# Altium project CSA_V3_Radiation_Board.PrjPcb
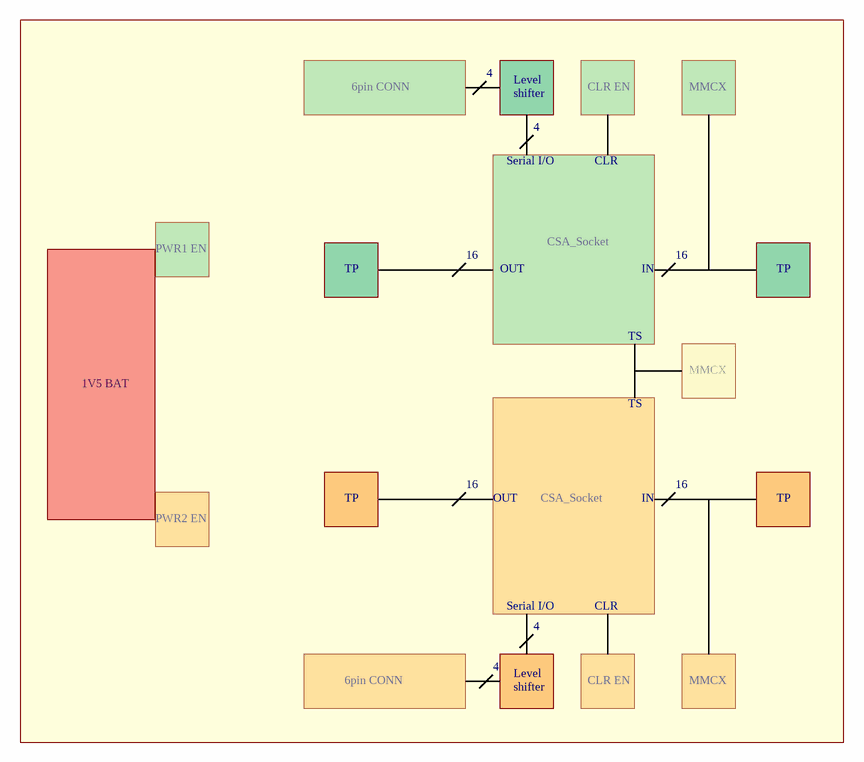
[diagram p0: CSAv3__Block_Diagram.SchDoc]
Approved_By: Gary S. Varner; BoardName: CSA_V3_Radiation_Board; Designer: AS/KPL; Drawn_By: KPL; IDLnum: IDL_16_016; ProjectName1: CSA_V3; RevNum: A
4 sheets, 186 parts. Net scope: flat (ports and power ports of the same name join across sheets).
Board file: IDL_16_016.PcbDoc
Sheets:
  PRJHdr_IDL_16_016.SchDoc
  CSAv3__Block_Diagram.SchDoc
  CSAv3_A1_Socket1.SchDoc
  CSAv3_A2_Socket2.SchDoc

## Sheet PRJHdr_IDL_16_016.SchDoc: Title_doc_parameter!
size 401 x 291 mm; DocumentNumber: 1; SheetNumber: 1; SheetTotal: 4; Project_IT-Code: XXXX

## Sheet CSAv3__Block_Diagram.SchDoc: Functional Block Schematic
size 401 x 291 mm; DocumentNumber: 2; SheetNumber: 2; SheetTotal: 4; PageSetup: Record=PageOptions¦CenterHorizontal=True¦CenterVertical=True¦PrintScale=1.00¦XCorrection=1.00¦YCorrection=1.00¦PrintKind=1¦BorderSize=5000000¦LeftOffset=0¦BottomOffset=0¦Orientation=2¦PaperLength=1000¦PaperWidth=1000¦Scale=100¦PaperSource=7¦PrintQuality=-3¦MediaType=1¦DitherType=10¦PrintScaleMode=1¦PaperKind=A4¦PaperIndex=9

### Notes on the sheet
- 6pin CONN
- 4
- Level
- shifter
- CLR EN
- MMCX
- Serial I/O
- CLR
- PWR1 EN
- CSA_Socket
- TP
- 16
- OUT
- IN
- 1V5 BAT
- TS
- PWR2 EN

## Sheet CSAv3_A1_Socket1.SchDoc: CSA_V3 Socket1/TS
size 401 x 291 mm; DocumentNumber: 3; SheetNumber: 3; SheetTotal: 4
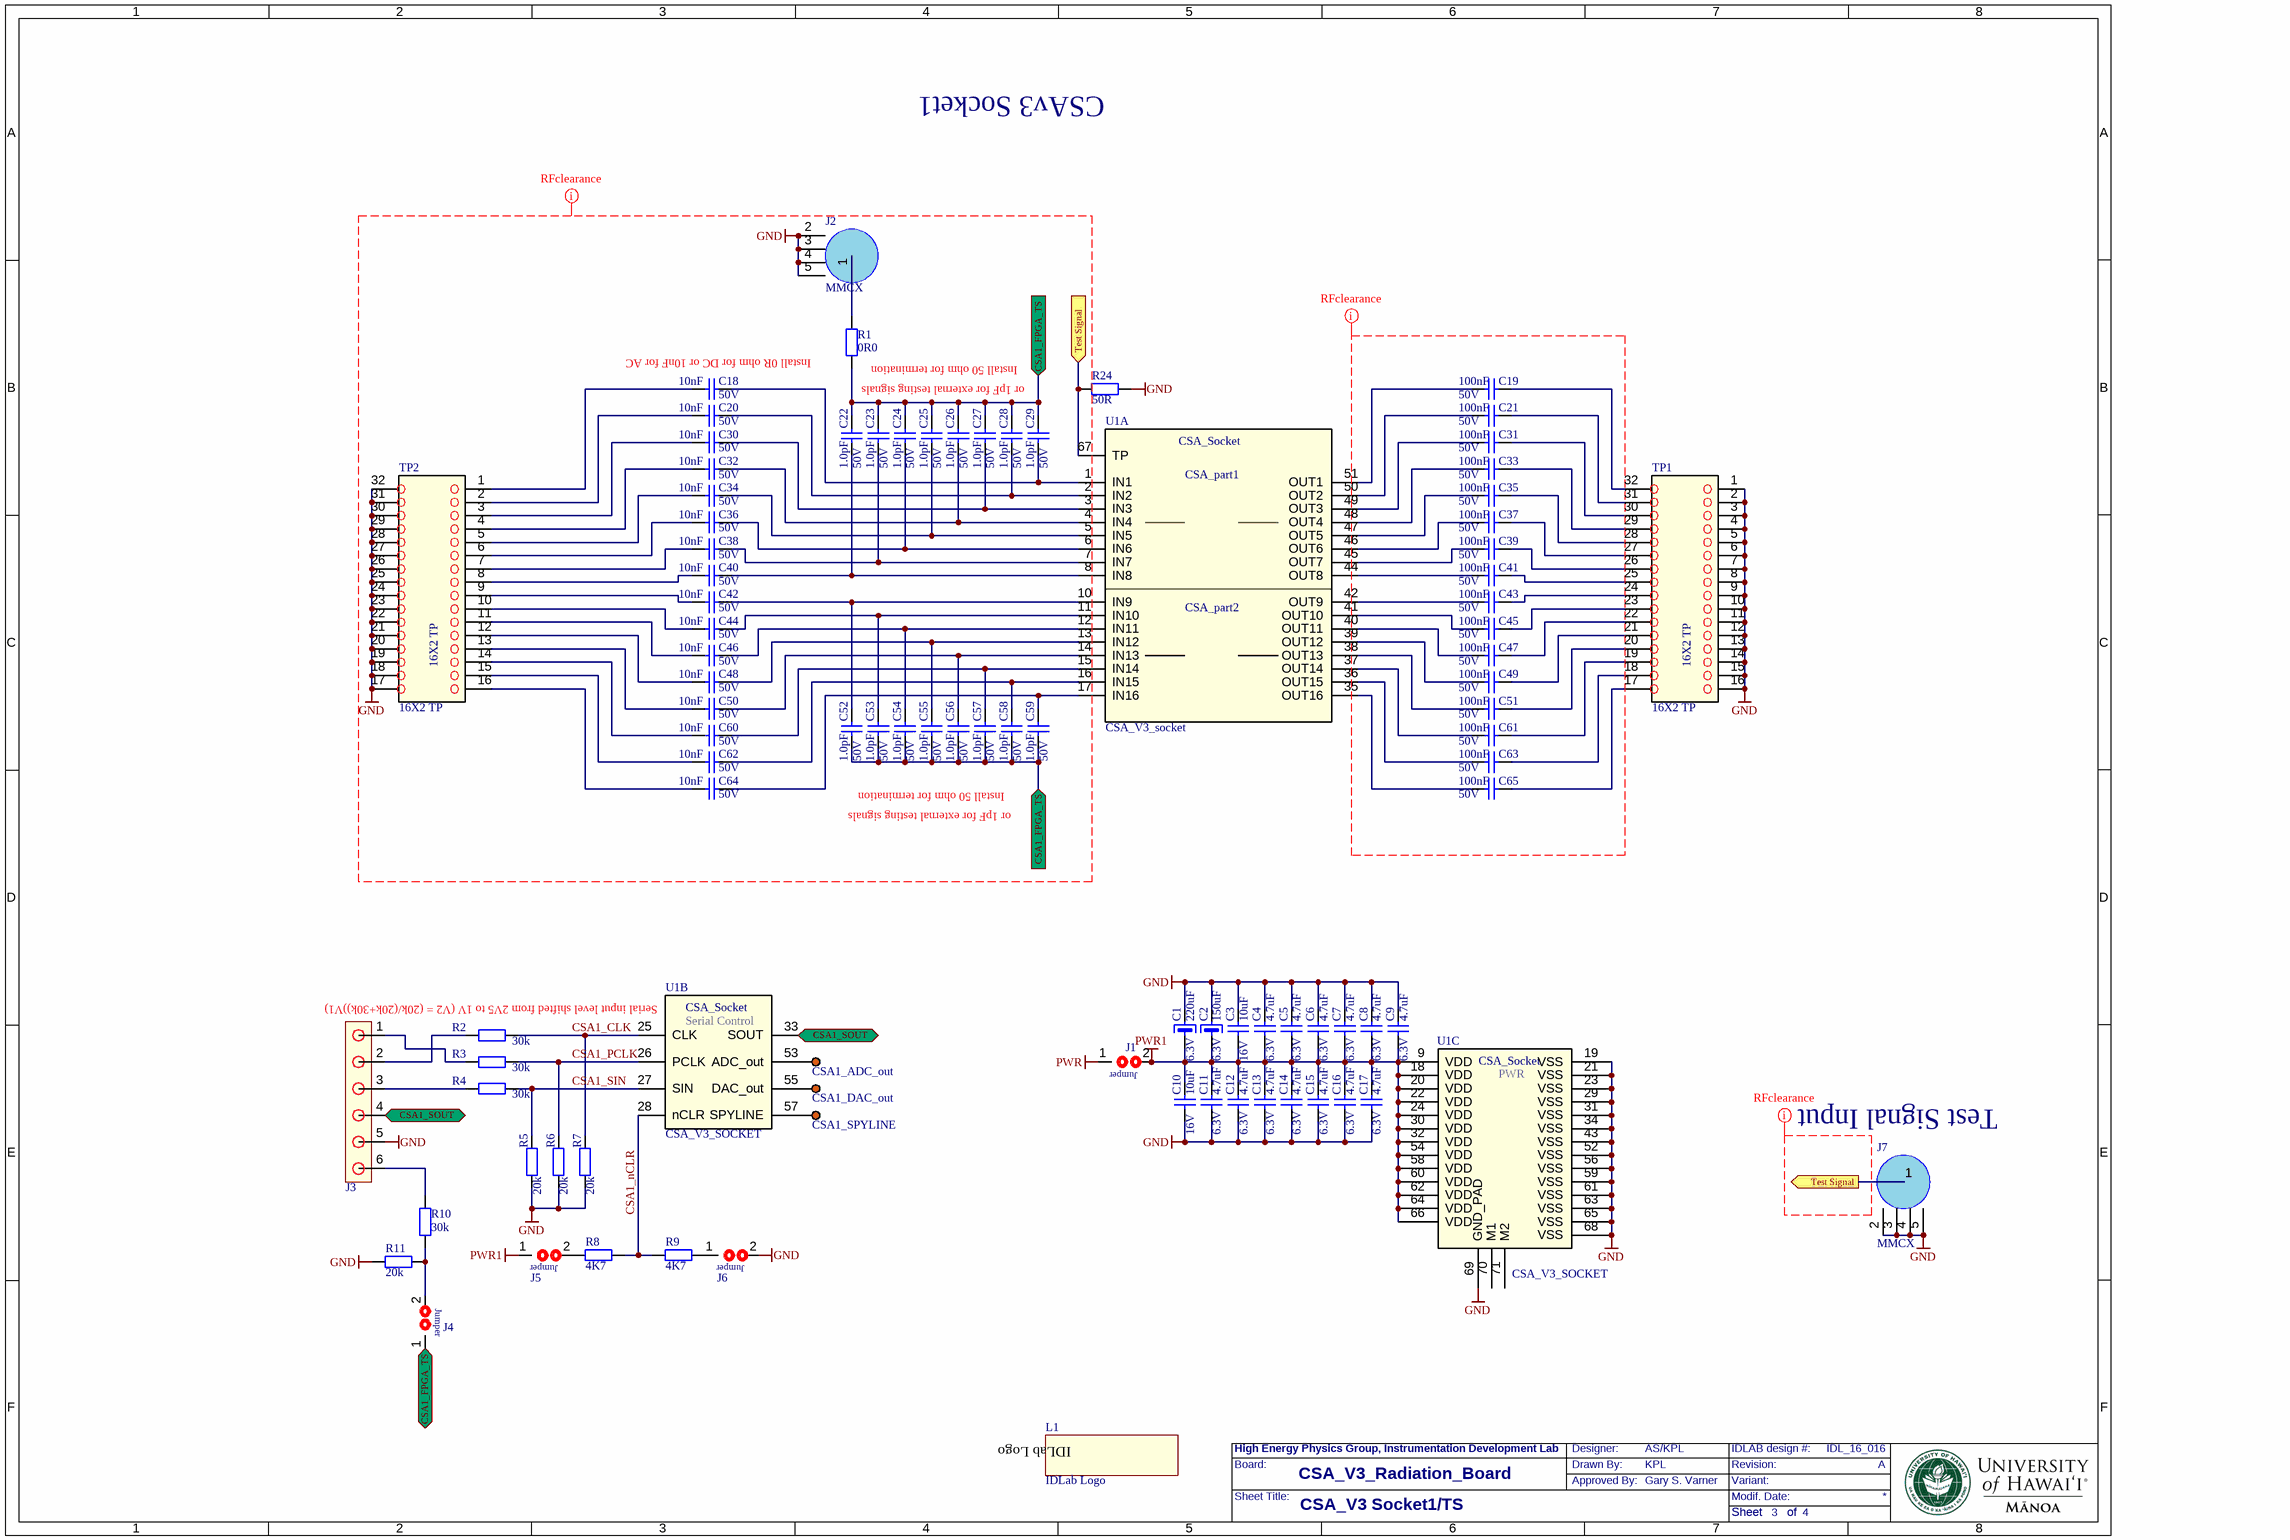
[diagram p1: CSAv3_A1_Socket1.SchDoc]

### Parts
C1  220uF  Voltage rating: 6.3V  [CTC-D7343-43]
C2  150uF  Voltage: 6.3V  [CTC-B3528-21]
C3  10uF  Voltage rating: 16V  [CC1206N1R]
C4  4.7uF  Voltage rating: 6.3V  [CC0402N1R]
C5  4.7uF  Voltage rating: 6.3V  [CC0402N1R]
C6  4.7uF  Voltage rating: 6.3V  [CC0402N1R]
C7  4.7uF  Voltage rating: 6.3V  [CC0402N1R]
C8  4.7uF  Voltage rating: 6.3V  [CC0402N1R]
C9  4.7uF  Voltage rating: 6.3V  [CC0402N1R]
C10  10uF  Voltage rating: 16V  [CC1206N1R]
C11  4.7uF  Voltage rating: 6.3V  [CC0402N1R]
C12  4.7uF  Voltage rating: 6.3V  [CC0402N1R]
C13  4.7uF  Voltage rating: 6.3V  [CC0402N1R]
C14  4.7uF  Voltage rating: 6.3V  [CC0402N1R]
C15  4.7uF  Voltage rating: 6.3V  [CC0402N1R]
C16  4.7uF  Voltage rating: 6.3V  [CC0402N1R]
C17  4.7uF  Voltage rating: 6.3V  [CC0402N1R]
C18  10nF  Voltage rating: 50V  [CC0402N1X]
C19  100nF  Voltage rating: 50V  [CC0402RF1]
C20  10nF  Voltage rating: 50V  [CC0402N1X]
C21  100nF  Voltage rating: 50V  [CC0402RF1]
C22  1.0pF  Voltage rating: 50V  [CC0402RF1]
C23  1.0pF  Voltage rating: 50V  [CC0402RF1]
C24  1.0pF  Voltage rating: 50V  [CC0402RF1]
C25  1.0pF  Voltage rating: 50V  [CC0402RF1]
C26  1.0pF  Voltage rating: 50V  [CC0402RF1]
C27  1.0pF  Voltage rating: 50V  [CC0402RF1]
C28  1.0pF  Voltage rating: 50V  [CC0402RF1]
C29  1.0pF  Voltage rating: 50V  [CC0402RF1]
C30  10nF  Voltage rating: 50V  [CC0402N1X]
C31  100nF  Voltage rating: 50V  [CC0402RF1]
C32  10nF  Voltage rating: 50V  [CC0402N1X]
C33  100nF  Voltage rating: 50V  [CC0402RF1]
C34  10nF  Voltage rating: 50V  [CC0402N1X]
C35  100nF  Voltage rating: 50V  [CC0402RF1]
C36  10nF  Voltage rating: 50V  [CC0402N1X]
C37  100nF  Voltage rating: 50V  [CC0402RF1]
C38  10nF  Voltage rating: 50V  [CC0402N1X]
C39  100nF  Voltage rating: 50V  [CC0402RF1]
C40  10nF  Voltage rating: 50V  [CC0402N1X]
C41  100nF  Voltage rating: 50V  [CC0402RF1]
C42  10nF  Voltage rating: 50V  [CC0402N1X]
C43  100nF  Voltage rating: 50V  [CC0402RF1]
C44  10nF  Voltage rating: 50V  [CC0402N1X]
C45  100nF  Voltage rating: 50V  [CC0402RF1]
C46  10nF  Voltage rating: 50V  [CC0402N1X]
C47  100nF  Voltage rating: 50V  [CC0402RF1]
C48  10nF  Voltage rating: 50V  [CC0402N1X]
C49  100nF  Voltage rating: 50V  [CC0402RF1]
C50  10nF  Voltage rating: 50V  [CC0402N1X]
C51  100nF  Voltage rating: 50V  [CC0402RF1]
C52  1.0pF  Voltage rating: 50V  [CC0402RF1]
C53  1.0pF  Voltage rating: 50V  [CC0402RF1]
C54  1.0pF  Voltage rating: 50V  [CC0402RF1]
C55  1.0pF  Voltage rating: 50V  [CC0402RF1]
C56  1.0pF  Voltage rating: 50V  [CC0402RF1]
C57  1.0pF  Voltage rating: 50V  [CC0402RF1]
C58  1.0pF  Voltage rating: 50V  [CC0402RF1]
C59  1.0pF  Voltage rating: 50V  [CC0402RF1]
C60  10nF  Voltage rating: 50V  [CC0402N1X]
C61  100nF  Voltage rating: 50V  [CC0402RF1]
C62  10nF  Voltage rating: 50V  [CC0402N1X]
C63  100nF  Voltage rating: 50V  [CC0402RF1]
C64  10nF  Voltage rating: 50V  [CC0402N1X]
C65  100nF  Voltage rating: 50V  [CC0402RF1]
CSA1_ADC_out  SP1.5S  [SP1.5SQ]  (value not drawn)  (no BOM)
CSA1_DAC_out  SP1.5S  [SP1.5SQ]  (value not drawn)  (no BOM)
CSA1_SPYLINE  SP1.5S  [SP1.5SQ]  (value not drawn)  (no BOM)
J1  2pin_Jumper  [2pin_jumper]  (value not drawn)
J2  MMCX  [MMCX_VERTICAL_THROUGH_HOLE]
J3  Male  (value not drawn)
J4  2pin_Jumper  [2pin_jumper]  (value not drawn)
J5  2pin_Jumper  [2pin_jumper]  (value not drawn)
J6  2pin_Jumper  [2pin_jumper]  (value not drawn)
J7  MMCX  [MMCX_VERTICAL_THROUGH_HOLE]
L1  IDLab Logo  [IDLab logo]
R1  0R0  [RC0603N1R]
R2  30k  [RC0603RF1]
R3  30k  [RC0603RF1]
R4  30k  [RC0603RF1]
R5  20k  [RC0603RF1]
R6  20k  [RC0603RF1]
R7  20k  [RC0603RF1]
R8  4K7  [RC0402N1R]
R9  4K7  [RC0402N1R]
R10  30k  [RC0603RF1]
R11  20k  [RC0603RF1]
R24  50R  [RC0402RF1]
TP1  16X2 TP  [16X2 TP]
TP2  16X2 TP  [16X2 TP]
U1  CSA_V3_socket  [SOCKET_QFN-68BT-0.5-01]  (parts A,B,C of 3)

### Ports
CSA1_FPGA_TS (in), CSA1_FPGA_TS (out), CSA1_SOUT (in), CSA1_SOUT (out), Test Signal (in), Test Signal (out)

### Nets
GND: C1.2 C2.2 C3.2 C4.2 C5.2 C6.2 C7.2 C8.2 C9.2 C10.1 C11.1 C12.1 C13.1 C14.1 C15.1 C16.1 C17.1 J2.2 J2.3 J2.4 J2.5 J3.5 J6.2 J7.2 J7.3 J7.4 J7.5 R5.1 R6.1 R7.1 R11.2 R24.1 TP1.1 TP1.2 TP1.3 TP1.4 TP1.5 TP1.6 TP1.7 TP1.8 TP1.9 TP1.10 TP1.11 TP1.12 TP1.13 TP1.14 TP1.15 TP1.16 TP2.17 TP2.18 TP2.19 TP2.20 TP2.21 TP2.22 TP2.23 TP2.24 TP2.25 TP2.26 TP2.27 TP2.28 TP2.29 TP2.30 TP2.31 TP2.32 U1.19(VSS) U1.21(VSS) U1.23(VSS) U1.29(VSS) U1.31(VSS) U1.34(VSS) U1.43(VSS) U1.52(VSS) U1.56(VSS) U1.59(VSS) U1.61(VSS) U1.63(VSS) U1.65(VSS) U1.68(VSS) U1.69(GND_PAD)
PWR: J1.1
PWR1: C1.1 C2.1 C3.1 C4.1 C5.1 C6.1 C7.1 C8.1 C9.1 C10.2 C11.2 C12.2 C13.2 C14.2 C15.2 C16.2 C17.2 J1.2 J5.1 U1.9(VDD) U1.18(VDD) U1.20(VDD) U1.22(VDD) U1.24(VDD) U1.30(VDD) U1.32(VDD) U1.54(VDD) U1.58(VDD) U1.60(VDD) U1.62(VDD) U1.64(VDD) U1.66(VDD)
CSA1_CLK: R2.2 R7.2 U1.25(CLK)  [project net CSA1_CLK_3]
CSA1_FPGA_TS: C22.2 C23.2 C24.2 C25.2 C26.2 C27.2 C28.2 C29.2 C52.1 C53.1 C54.1 C55.1 C56.1 C57.1 C58.1 C59.1 J4.1 R1.2 ; port CSA1_FPGA_TS
CSA1_nCLR: R8.1 R9.2 U1.28(nCLR)  [project net CSA1_nCLR_3]
CSA1_PCLK: R3.2 R6.2 U1.26(PCLK)  [project net CSA1_PCLK_3]
CSA1_SIN: R4.2 R5.2 U1.27(SIN)  [project net CSA1_SIN_3]
CSA1_SOUT: J3.4 U1.33(SOUT) ; port CSA1_SOUT
Test Signal: J7.1 R24.2 U1.67(TP) ; port Test Signal
NetC18_1: C18.1 TP2.1
NetC18_2: C18.2 C29.1 U1.1(IN1)
NetC19_1: C19.1 U1.51(OUT1)
NetC19_2: C19.2 TP1.32
NetC20_1: C20.1 TP2.2
NetC20_2: C20.2 C28.1 U1.2(IN2)
NetC21_1: C21.1 U1.50(OUT2)
NetC21_2: C21.2 TP1.31
NetC22_1: C22.1 C40.2 U1.8(IN8)
NetC23_1: C23.1 C38.2 U1.7(IN7)
NetC24_1: C24.1 C36.2 U1.6(IN6)
NetC25_1: C25.1 C34.2 U1.5(IN5)
NetC26_1: C26.1 C32.2 U1.4(IN4)
NetC27_1: C27.1 C30.2 U1.3(IN3)
NetC30_1: C30.1 TP2.3
NetC31_1: C31.1 U1.49(OUT3)
NetC31_2: C31.2 TP1.30
NetC32_1: C32.1 TP2.4
NetC33_1: C33.1 U1.48(OUT4)
NetC33_2: C33.2 TP1.29
NetC34_1: C34.1 TP2.5
NetC35_1: C35.1 U1.47(OUT5)
NetC35_2: C35.2 TP1.28
NetC36_1: C36.1 TP2.6
NetC37_1: C37.1 U1.46(OUT6)
NetC37_2: C37.2 TP1.27
NetC38_1: C38.1 TP2.7
NetC39_1: C39.1 U1.45(OUT7)
NetC39_2: C39.2 TP1.26
NetC40_1: C40.1 TP2.8
NetC41_1: C41.1 U1.44(OUT8)
NetC41_2: C41.2 TP1.25
NetC42_1: C42.1 TP2.9
NetC42_2: C42.2 C52.2 U1.10(IN9)
NetC43_1: C43.1 U1.42(OUT9)
NetC43_2: C43.2 TP1.24
NetC44_1: C44.1 TP2.10
NetC44_2: C44.2 C53.2 U1.11(IN10)
NetC45_1: C45.1 U1.41(OUT10)
NetC45_2: C45.2 TP1.23
NetC46_1: C46.1 TP2.11
NetC46_2: C46.2 C54.2 U1.12(IN11)
NetC47_1: C47.1 U1.40(OUT11)
NetC47_2: C47.2 TP1.22
NetC48_1: C48.1 TP2.12
NetC48_2: C48.2 C55.2 U1.13(IN12)
NetC49_1: C49.1 U1.39(OUT12)
NetC49_2: C49.2 TP1.21
NetC50_1: C50.1 TP2.13
NetC50_2: C50.2 C56.2 U1.14(IN13)
NetC51_1: C51.1 U1.38(OUT13)
NetC51_2: C51.2 TP1.20
NetC57_2: C57.2 C60.2 U1.15(IN14)
NetC58_2: C58.2 C62.2 U1.16(IN15)
NetC59_2: C59.2 C64.2 U1.17(IN16)
NetC60_1: C60.1 TP2.14
NetC61_1: C61.1 U1.37(OUT14)
NetC61_2: C61.2 TP1.19
NetC62_1: C62.1 TP2.15
NetC63_1: C63.1 U1.36(OUT15)
NetC63_2: C63.2 TP1.18
NetC64_1: C64.1 TP2.16
NetC65_1: C65.1 U1.35(OUT16)
NetC65_2: C65.2 TP1.17
NetCSA1_ADC_out_1: CSA1_ADC_out.1 U1.53(ADC_out)
NetCSA1_DAC_out_1: CSA1_DAC_out.1 U1.55(DAC_out)
NetCSA1_SPYLINE_1: CSA1_SPYLINE.1 U1.57(SPYLINE)
NetJ2_1: J2.1 R1.1
NetJ3_1: J3.1 R3.1
NetJ3_2: J3.2 R2.1
NetJ3_3: J3.3 R4.1
NetJ3_6: J3.6 R10.2
NetJ4_2: J4.2 R10.1 R11.1
NetJ5_2: J5.2 R8.2
NetJ6_1: J6.1 R9.1

Not connected (* = marked no-connect by the designer): U1 70(M1) 71(M2)

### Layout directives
net class RF: (no net found under the mark), GND

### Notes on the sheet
- CSAv3 Socket1
- (near C18) Install 0R ohm for DC or 10nF for AC
- (near R1) Install 50 ohm for termination
- or 1pF for external testing signals
- Install 50 ohm for termination
- Serial input level shifted from 2V5 to 1V (V2 = (20k/(20k+30k))V1)
- (near J7) Test Signal Input

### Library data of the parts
C1 = CAPT7343_220U_6.3V: 220µF 6.3V Aluminum - Polymer Capacitors; Manufacturer: Panasonic; Manufacturer No: EEF-UE0J221LR; Tech: SMDR
C2 = CAPT3528_150U6V3R0.5: 150µF Molded Tantalum Capacitors 6.3V 1411; Manufacturer: AVX; Manufacturer No: F930J157MBA; Comment2: 6.3V 0.5R  20%; Tech: SMDR
C3 C10 = CAPCC1206_10U_16VX7R: 10µF 16V Ceramic Capacitor X7R 1206; Manufacturer: TDK; Manufacturer No: C3216X7R1C106M160AC; Tech: SMDR
C4-C9 C11-C17 = CAPCC0402_4.7uF_6.3V: 4.7µF ±10% 6.3V X7R Ceramic Capacitor; Manufacturer: Samsung Electro-Mechanics America, Inc.; Manufacturer No: CL05A475KQ5NRNC; Tech: SMDR
C18 C20 C30 C32 C34 C36 C38 C40 C42 C44 C46 C48 C50 C60 C62 C64 = CAPCC0402_1_10.0N_50VX7R: Capacitor chip ceramic 0402 50V X7R; Manufacturer: Murata; Manufacturer No: GRM155R71H103KA88J; Tech: SMDR
C19 C21 C31 C33 C35 C37 C39 C41 C43 C45 C47 C49 C51 C61 C63 C65 = CAP0402_100N_50VX7R: Capacitor chip ceramic 0402 50V X7R; Manufacturer: TDK; Manufacturer No: C1005X7R1H104K050BB; Tech: SMDR
C22-C29 C52-C59 = CAP0402_1P_50VNP0: Capacitor chip ceramic 0402 50V NPO; Manufacturer: Murata; Manufacturer No: GRM1555C1H1R0CA01D; Tech: SMDR
CSA1_ADC_out CSA1_DAC_out CSA1_SPYLINE = SP1.5S: Wire solder pin 1.5mm; Sort: 610; Tech: THDW
J1 J4-J6 = 2pin_Jumper: 2 Positions Header, Unshrouded, Breakaway Connector 0.100" (2.54mm) Through Hole Tin; Manufacturer: Harwin Inc.; Manufacturer No: M20-9990246; Voltage rating: 50V
J2 J7 = MMCX: CONN MMCX JACK STR 50 OHM PCB; Manufacturer: Molex, LLC; Manufacturer part #: 0734151471
J3 = CONN_6pin_Molex 2.54mm: 6 Positions Header, Unshrouded Connector 0.100" (2.54mm) Through Hole Tin; Manufacturer: Molex, LLC; Manufacturer No: 0022232061
R1 = RES0603-0R0-1%100PPM: RES SMD 0.0OHM JUMPER 1/10W 0603; Manufacturer: Panasonic; Manufacturer No: ERJ-3GEY0R00V; Tech: SMDR
R2-R4 R10 = RES0603-30K-1%100PPM: RES SMD 30K OHM 1% 1/10W 0603; Manufacturer: Yageo; Manufacturer No: RC0603FR-0730KL; Tech: SMDR
R5-R7 R11 = RES0603-20K-1%100PPM: RES SMD 20K OHM 1% 1/10W 0603; Manufacturer: Yageo; Manufacturer No: RC0603FR-0720KL; Tech: SMDR
R8 R9 = RES0402-4.7K-1%100PPM: RES SMD 4.7K OHM 1% 1/10W 0402; Manufacturer: Panasonic; Manufacturer No: ERJ-2RKF4701X; Tech: SMDR
R24 = RES0402-50R-1%100PPM: RES SMD 49.9 OHM 1% 1/16W 0402; Manufacturer: Samsung Inc.; Manufacturer No: RC1005F49R9CS; Tech: SMDR
TP1 TP2 = TP 16X2: 16X2 TESTPOINTs; Voltage rating: 50V
U1 = CSA_V3_socket: Enplas IC Test & Burn-in Socket, for QFN68, MLP68, MLF68 package; Manufacturer: Enplas Co; Manufacturer No: QFN-68BT-0.5-01; Tech: through hole

## Sheet CSAv3_A2_Socket2.SchDoc: CSA_V3 Socket2/BATT_PWR
size 401 x 291 mm; DocumentNumber: 4; SheetNumber: 4; SheetTotal: 4
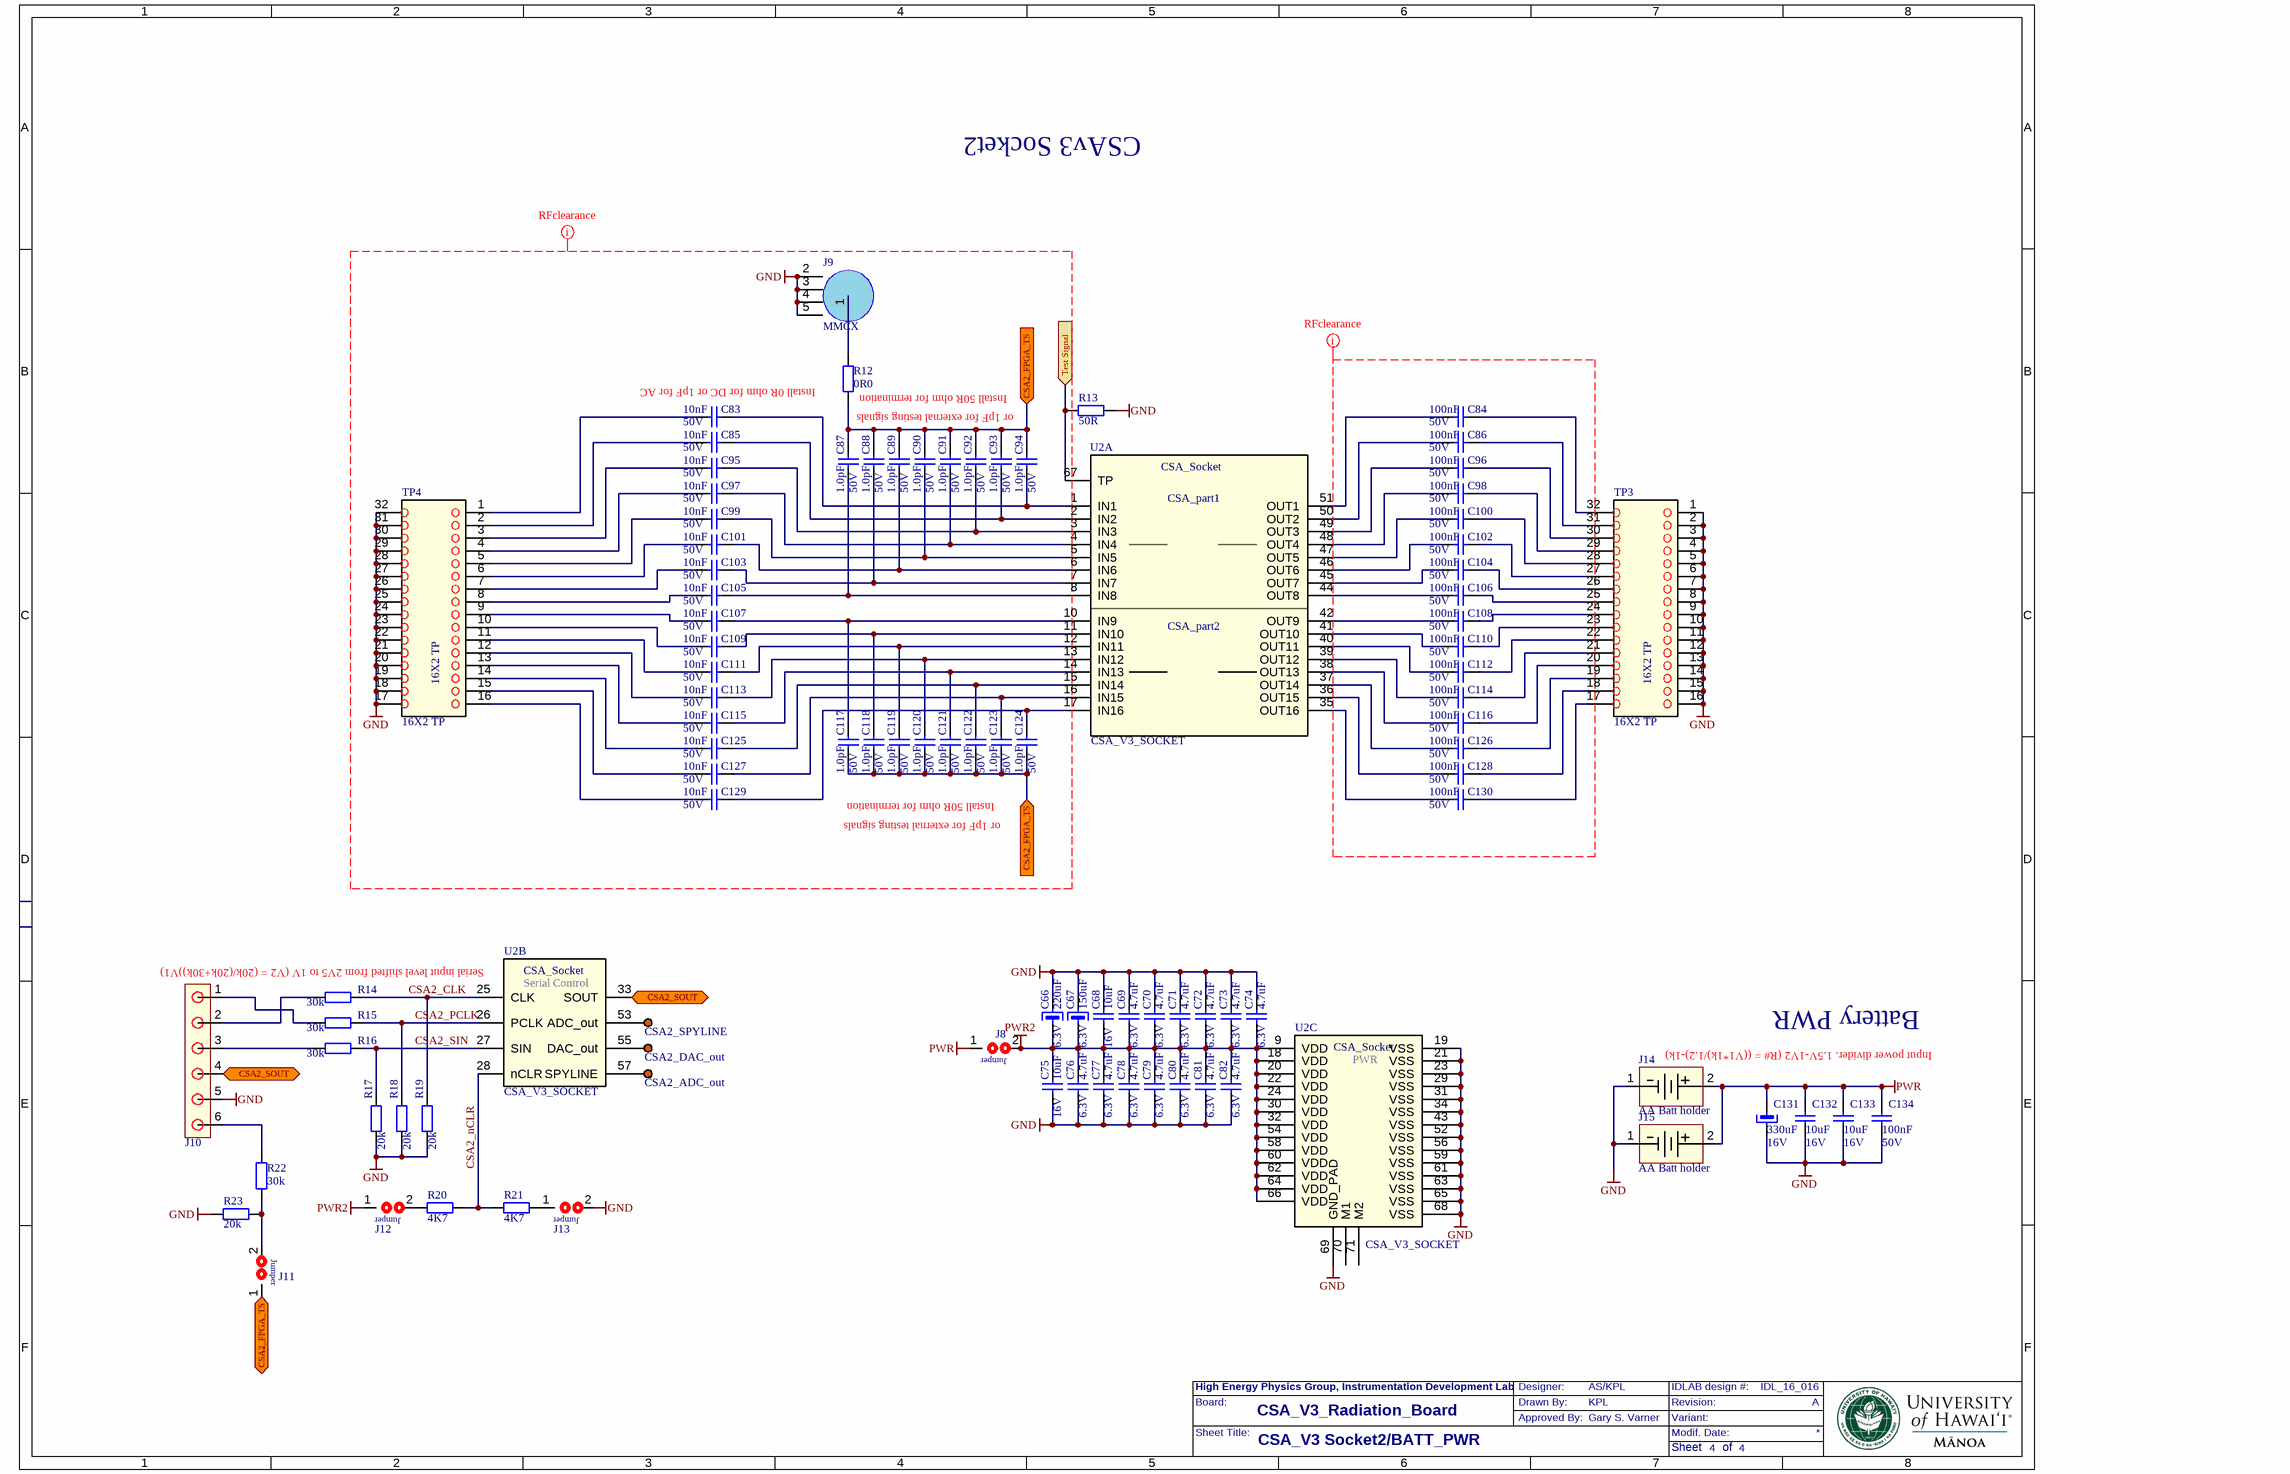
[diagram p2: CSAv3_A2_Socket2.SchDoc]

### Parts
C66  220uF  Voltage rating: 6.3V  [CTC-D7343-43]
C67  150uF  Voltage: 6.3V  [CTC-B3528-21]
C68  10uF  Voltage rating: 16V  [CC1206N1R]
C69  4.7uF  Voltage rating: 6.3V  [CC0402N1R]
C70  4.7uF  Voltage rating: 6.3V  [CC0402N1R]
C71  4.7uF  Voltage rating: 6.3V  [CC0402N1R]
C72  4.7uF  Voltage rating: 6.3V  [CC0402N1R]
C73  4.7uF  Voltage rating: 6.3V  [CC0402N1R]
C74  4.7uF  Voltage rating: 6.3V  [CC0402N1R]
C75  10uF  Voltage rating: 16V  [CC1206N1R]
C76  4.7uF  Voltage rating: 6.3V  [CC0402N1R]
C77  4.7uF  Voltage rating: 6.3V  [CC0402N1R]
C78  4.7uF  Voltage rating: 6.3V  [CC0402N1R]
C79  4.7uF  Voltage rating: 6.3V  [CC0402N1R]
C80  4.7uF  Voltage rating: 6.3V  [CC0402N1R]
C81  4.7uF  Voltage rating: 6.3V  [CC0402N1R]
C82  4.7uF  Voltage rating: 6.3V  [CC0402N1R]
C83  10nF  Voltage rating: 50V  [CC0402N1X]
C84  100nF  Voltage rating: 50V  [CC0402RF1]
C85  10nF  Voltage rating: 50V  [CC0402N1X]
C86  100nF  Voltage rating: 50V  [CC0402RF1]
C87  1.0pF  Voltage rating: 50V  [CC0402RF1]
C88  1.0pF  Voltage rating: 50V  [CC0402RF1]
C89  1.0pF  Voltage rating: 50V  [CC0402RF1]
C90  1.0pF  Voltage rating: 50V  [CC0402RF1]
C91  1.0pF  Voltage rating: 50V  [CC0402RF1]
C92  1.0pF  Voltage rating: 50V  [CC0402RF1]
C93  1.0pF  Voltage rating: 50V  [CC0402RF1]
C94  1.0pF  Voltage rating: 50V  [CC0402RF1]
C95  10nF  Voltage rating: 50V  [CC0402N1X]
C96  100nF  Voltage rating: 50V  [CC0402RF1]
C97  10nF  Voltage rating: 50V  [CC0402N1X]
C98  100nF  Voltage rating: 50V  [CC0402RF1]
C99  10nF  Voltage rating: 50V  [CC0402N1X]
C100  100nF  Voltage rating: 50V  [CC0402RF1]
C101  10nF  Voltage rating: 50V  [CC0402N1X]
C102  100nF  Voltage rating: 50V  [CC0402RF1]
C103  10nF  Voltage rating: 50V  [CC0402N1X]
C104  100nF  Voltage rating: 50V  [CC0402RF1]
C105  10nF  Voltage rating: 50V  [CC0402N1X]
C106  100nF  Voltage rating: 50V  [CC0402RF1]
C107  10nF  Voltage rating: 50V  [CC0402N1X]
C108  100nF  Voltage rating: 50V  [CC0402RF1]
C109  10nF  Voltage rating: 50V  [CC0402N1X]
C110  100nF  Voltage rating: 50V  [CC0402RF1]
C111  10nF  Voltage rating: 50V  [CC0402N1X]
C112  100nF  Voltage rating: 50V  [CC0402RF1]
C113  10nF  Voltage rating: 50V  [CC0402N1X]
C114  100nF  Voltage rating: 50V  [CC0402RF1]
C115  10nF  Voltage rating: 50V  [CC0402N1X]
C116  100nF  Voltage rating: 50V  [CC0402RF1]
C117  1.0pF  Voltage rating: 50V  [CC0402RF1]
C118  1.0pF  Voltage rating: 50V  [CC0402RF1]
C119  1.0pF  Voltage rating: 50V  [CC0402RF1]
C120  1.0pF  Voltage rating: 50V  [CC0402RF1]
C121  1.0pF  Voltage rating: 50V  [CC0402RF1]
C122  1.0pF  Voltage rating: 50V  [CC0402RF1]
C123  1.0pF  Voltage rating: 50V  [CC0402RF1]
C124  1.0pF  Voltage rating: 50V  [CC0402RF1]
C125  10nF  Voltage rating: 50V  [CC0402N1X]
C126  100nF  Voltage rating: 50V  [CC0402RF1]
C127  10nF  Voltage rating: 50V  [CC0402N1X]
C128  100nF  Voltage rating: 50V  [CC0402RF1]
C129  10nF  Voltage rating: 50V  [CC0402N1X]
C130  100nF  Voltage rating: 50V  [CC0402RF1]
C131  330uF  Voltage rating: 16V  [CTC-D7343-43]
C132  10uF  Voltage rating: 16V  [CC1206N1R]
C133  10uF  Voltage rating: 16V  [CC1206N1R]
C134  100nF  Voltage rating: 50V  [CC0402RF1]
CSA2_ADC_out  SP1.5S  [SP1.5SQ]  (value not drawn)  (no BOM)
CSA2_DAC_out  SP1.5S  [SP1.5SQ]  (value not drawn)  (no BOM)
CSA2_SPYLINE  SP1.5S  [SP1.5SQ]  (value not drawn)  (no BOM)
J8  2pin_Jumper  [2pin_jumper]  (value not drawn)
J9  MMCX  [MMCX_VERTICAL_THROUGH_HOLE]
J10  Male  [Molex 6POS]  (value not drawn)
J11  2pin_Jumper  [2pin_jumper]  (value not drawn)
J12  2pin_Jumper  [2pin_jumper]  (value not drawn)
J13  2pin_Jumper  [2pin_jumper]  (value not drawn)
J14  AA Batt holder  [Batt_pack_AA]
J15  AA Batt holder  [Batt_pack_AA]
R12  0R0  [RC0603N1R]
R13  50R  [RC0402RF1]
R14  30k  [RC0603RF1]
R15  30k  [RC0603RF1]
R16  30k  [RC0603RF1]
R17  20k  [RC0603RF1]
R18  20k  [RC0603RF1]
R19  20k  [RC0603RF1]
R20  4K7  [RC0402N1R]
R21  4K7  [RC0402N1R]
R22  30k  [RC0603RF1]
R23  20k  [RC0603RF1]
TP3  16X2 TP  [16X2 TP]
TP4  16X2 TP  [16X2 TP]
U2  CSA_V3_SOCKET  [SOCKET_QFN-68BT-0.5-01]  (parts A,B,C of 3)

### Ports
CSA2_FPGA_TS (in), CSA2_FPGA_TS (out), CSA2_SOUT (in), CSA2_SOUT (out), Test Signal (in)

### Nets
GND: C66.2 C67.2 C68.2 C69.2 C70.2 C71.2 C72.2 C73.2 C74.2 C75.1 C76.1 C77.1 C78.1 C79.1 C80.1 C81.1 C82.1 C131.2 C132.1 C133.1 C134.1 J9.2 J9.3 J9.4 J9.5 J10.5 J13.2 J14.1 J15.1 R13.1 R17.1 R18.1 R19.1 R23.2 TP3.1 TP3.2 TP3.3 TP3.4 TP3.5 TP3.6 TP3.7 TP3.8 TP3.9 TP3.10 TP3.11 TP3.12 TP3.13 TP3.14 TP3.15 TP3.16 TP4.17 TP4.18 TP4.19 TP4.20 TP4.21 TP4.22 TP4.23 TP4.24 TP4.25 TP4.26 TP4.27 TP4.28 TP4.29 TP4.30 TP4.31 TP4.32 U2.19(VSS) U2.21(VSS) U2.23(VSS) U2.29(VSS) U2.31(VSS) U2.34(VSS) U2.43(VSS) U2.52(VSS) U2.56(VSS) U2.59(VSS) U2.61(VSS) U2.63(VSS) U2.65(VSS) U2.68(VSS) U2.69(GND_PAD)
PWR: C131.1 C132.2 C133.2 C134.2 J8.1 J14.2 J15.2
PWR2: C66.1 C67.1 C68.1 C69.1 C70.1 C71.1 C72.1 C73.1 C74.1 C75.2 C76.2 C77.2 C78.2 C79.2 C80.2 C81.2 C82.2 J8.2 J12.1 U2.9(VDD) U2.18(VDD) U2.20(VDD) U2.22(VDD) U2.24(VDD) U2.30(VDD) U2.32(VDD) U2.54(VDD) U2.58(VDD) U2.60(VDD) U2.62(VDD) U2.64(VDD) U2.66(VDD)
CSA2_CLK: R14.2 R19.2 U2.25(CLK)  [project net CSA2_CLK_4]
CSA2_FPGA_TS: C87.2 C88.2 C89.2 C90.2 C91.2 C92.2 C93.2 C94.2 C117.1 C118.1 C119.1 C120.1 C121.1 C122.1 C123.1 C124.1 J11.1 R12.2 ; port CSA2_FPGA_TS
CSA2_nCLR: R20.1 R21.2 U2.28(nCLR)  [project net CSA2_nCLR_4]
CSA2_PCLK: R15.2 R18.2 U2.26(PCLK)  [project net CSA2_PCLK_4]
CSA2_SIN: R16.2 R17.2 U2.27(SIN)  [project net CSA2_SIN_4]
CSA2_SOUT: J10.4 U2.33(SOUT) ; port CSA2_SOUT
Test Signal: R13.2 U2.67(TP) ; port Test Signal
NetC83_1: C83.1 TP4.1
NetC83_2: C83.2 C94.1 U2.1(IN1)
NetC84_1: C84.1 U2.51(OUT1)
NetC84_2: C84.2 TP3.32
NetC85_1: C85.1 TP4.2
NetC85_2: C85.2 C93.1 U2.2(IN2)
NetC86_1: C86.1 U2.50(OUT2)
NetC86_2: C86.2 TP3.31
NetC87_1: C87.1 C105.2 U2.8(IN8)
NetC88_1: C88.1 C103.2 U2.7(IN7)
NetC89_1: C89.1 C101.2 U2.6(IN6)
NetC90_1: C90.1 C99.2 U2.5(IN5)
NetC91_1: C91.1 C97.2 U2.4(IN4)
NetC92_1: C92.1 C95.2 U2.3(IN3)
NetC95_1: C95.1 TP4.3
NetC96_1: C96.1 U2.49(OUT3)
NetC96_2: C96.2 TP3.30
NetC97_1: C97.1 TP4.4
NetC98_1: C98.1 U2.48(OUT4)
NetC98_2: C98.2 TP3.29
NetC99_1: C99.1 TP4.5
NetC100_1: C100.1 U2.47(OUT5)
NetC100_2: C100.2 TP3.28
NetC101_1: C101.1 TP4.6
NetC102_1: C102.1 U2.46(OUT6)
NetC102_2: C102.2 TP3.27
NetC103_1: C103.1 TP4.7
NetC104_1: C104.1 U2.45(OUT7)
NetC104_2: C104.2 TP3.26
NetC105_1: C105.1 TP4.8
NetC106_1: C106.1 U2.44(OUT8)
NetC106_2: C106.2 TP3.25
NetC107_1: C107.1 TP4.9
NetC107_2: C107.2 C117.2 U2.10(IN9)
NetC108_1: C108.1 U2.42(OUT9)
NetC108_2: C108.2 TP3.24
NetC109_1: C109.1 TP4.10
NetC109_2: C109.2 C118.2 U2.11(IN10)
NetC110_1: C110.1 U2.41(OUT10)
NetC110_2: C110.2 TP3.23
NetC111_1: C111.1 TP4.11
NetC111_2: C111.2 C119.2 U2.12(IN11)
NetC112_1: C112.1 U2.40(OUT11)
NetC112_2: C112.2 TP3.22
NetC113_1: C113.1 TP4.12
NetC113_2: C113.2 C120.2 U2.13(IN12)
NetC114_1: C114.1 U2.39(OUT12)
NetC114_2: C114.2 TP3.21
NetC115_1: C115.1 TP4.13
NetC115_2: C115.2 C121.2 U2.14(IN13)
NetC116_1: C116.1 U2.38(OUT13)
NetC116_2: C116.2 TP3.20
NetC122_2: C122.2 C125.2 U2.15(IN14)
NetC123_2: C123.2 C127.2 U2.16(IN15)
NetC124_2: C124.2 C129.2 U2.17(IN16)
NetC125_1: C125.1 TP4.14
NetC126_1: C126.1 U2.37(OUT14)
NetC126_2: C126.2 TP3.19
NetC127_1: C127.1 TP4.15
NetC128_1: C128.1 U2.36(OUT15)
NetC128_2: C128.2 TP3.18
NetC129_1: C129.1 TP4.16
NetC130_1: C130.1 U2.35(OUT16)
NetC130_2: C130.2 TP3.17
NetCSA2_ADC_out_1: CSA2_ADC_out.1 U2.57(SPYLINE)
NetCSA2_DAC_out_1: CSA2_DAC_out.1 U2.55(DAC_out)
NetCSA2_SPYLINE_1: CSA2_SPYLINE.1 U2.53(ADC_out)
NetJ9_1: J9.1 R12.1
NetJ10_1: J10.1 R15.1
NetJ10_2: J10.2 R14.1
NetJ10_3: J10.3 R16.1
NetJ10_6: J10.6 R22.2
NetJ11_2: J11.2 R22.1 R23.1
NetJ12_2: J12.2 R20.2
NetJ13_1: J13.1 R21.1

Not connected (* = marked no-connect by the designer): J14 3(MH1) 4(MH2) 5(MH3); J15 3(MH1) 4(MH2) 5(MH3); U2 70(M1) 71(M2)

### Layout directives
net class RF: (no net found under the mark), GND

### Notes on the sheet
- CSAv3 Socket2
- Install 0R ohm for DC or 1pF for AC
- (near R12) Install 50R ohm for termination
- or 1pF for external testing signals
- Install 50R ohm for termination
- Serial input level shifted from 2V5 to 1V (V2 = (20k/(20k+30k))V1)
- Battery PWR
- (near J14) Input power divider. 1.5V-1V2 (R# = ((V1*1k)/1.2)-1k)

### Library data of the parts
C66 = CAPT7343_220U_6.3V: as C1 on sheet CSAv3_A1_Socket1
C67 = CAPT3528_150U6V3R0.5: as C2 on sheet CSAv3_A1_Socket1
C68 C75 C132 C133 = CAPCC1206_10U_16VX7R: as C3 on sheet CSAv3_A1_Socket1
C69-C74 C76-C82 = CAPCC0402_4.7uF_6.3V: as C4 on sheet CSAv3_A1_Socket1
C83 C85 C95 C97 C99 C101 C103 C105 C107 C109 C111 C113 C115 C125 C127 C129 = CAPCC0402_1_10.0N_50VX7R: as C18 on sheet CSAv3_A1_Socket1
C84 C86 C96 C98 C100 C102 C104 C106 C108 C110 C112 C114 C116 C126 C128 C130 C134 = CAP0402_100N_50VX7R: as C19 on sheet CSAv3_A1_Socket1
C87-C94 C117-C124 = CAP0402_1P_50VNP0: as C22 on sheet CSAv3_A1_Socket1
C131 = CAPT7343_330U_16V: 330µF Molded Tantalum - Polymer Capacitors 16V; Manufacturer: Kemet; Manufacturer No: T521X337M016ATE050; Tech: SMDR
CSA2_ADC_out CSA2_DAC_out CSA2_SPYLINE = SP1.5S: as CSA1_ADC_out on sheet CSAv3_A1_Socket1
J8 J11-J13 = 2pin_Jumper: as J1 on sheet CSAv3_A1_Socket1
J9 = MMCX: as J2 on sheet CSAv3_A1_Socket1
J10 = CONN_6pin_Molex 2.54mm: as J3 on sheet CSAv3_A1_Socket1
J14 J15 = Batt_pack_AA: HOLDER BATTERY 1/AA CELL PC MNT; Manufacturer: MPD (Memory Protection Devices); Manufacturer No: BHAA-3; Tech: Through Hole
R12 = RES0603-0R0-1%100PPM: as R1 on sheet CSAv3_A1_Socket1
R13 = RES0402-50R-1%100PPM: as R24 on sheet CSAv3_A1_Socket1
R14-R16 R22 = RES0603-30K-1%100PPM: as R2 on sheet CSAv3_A1_Socket1
R17-R19 R23 = RES0603-20K-1%100PPM: as R5 on sheet CSAv3_A1_Socket1
R20 R21 = RES0402-4.7K-1%100PPM: as R8 on sheet CSAv3_A1_Socket1
TP3 TP4 = TP 16X2: 16X2 TESTPOINTs; Voltage rating: 50V
U2 = CSA_V3_socket: as U1 on sheet CSAv3_A1_Socket1

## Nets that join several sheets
GND: CSAv3_A1_Socket1 (79 pins), CSAv3_A2_Socket2 (81 pins)
PWR: CSAv3_A1_Socket1 (J1.1), CSAv3_A2_Socket2 (7 pins)
Test Signal: CSAv3_A1_Socket1 (J7.1 R24.2 U1.67), CSAv3_A2_Socket2 (R13.2 U2.67)

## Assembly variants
Single-Ended Input: not fitted C2 C4 C9 C10 C19 C20 C22 C24 C29 C30 C39 C40 C42 C45 C50 C52 C54 C59 C60 C69 C70 C72 C74 C79 C80 C89 C90 C92 C95 C100 C102 C104 C109 C110 C119 C120 C122 C124 C129 C130 C139 C140 C142 C145 C150 HS1 R3 R5 R7 R23 R25 R39 R50 R52 R68 R70 R84 R95 R97 R113 R115 R129 R164 R165 R166 R167 R168 R169 R170 R171 R172 R173 R174 R175 R176 R177 R178 TIP1
Differential Input: not fitted C2 C4 C19 C20 C22 C24 C39 C40 C42 C50 C52 C54 C69 C70 C72 C74 C89 C90 C92 C100 C102 C104 C119 C120 C122 C124 C139 C140 C142 C150 HS1 R4 R5 R7 R13 R14 R21 R22 R23 R25 R31 R32 R38 R39 R48 R49 R50 R52 R58 R59 R66 R67 R68 R70 R76 R77 R83 R84 R88 R93 R94 R95 R97 R103 R104 R111 R112 R113 R115 R121 R122 R128 R129 R133 R164 R333 TIP1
